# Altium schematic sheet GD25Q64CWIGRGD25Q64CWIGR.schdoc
size 127 x 101 mm
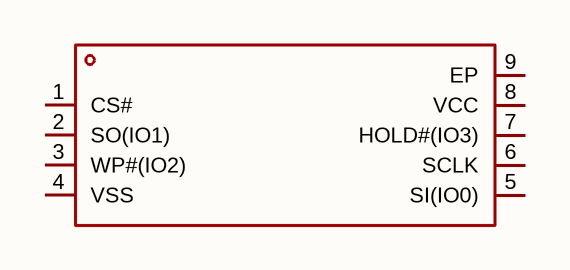
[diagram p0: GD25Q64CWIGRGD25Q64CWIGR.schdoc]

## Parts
U?  gd25q64cwigr  [WSON-8_L6.0-W5.0-P1.27-BL-EP]  (value not drawn)

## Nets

Not connected (* = marked no-connect by the designer): U? 1(CS#) 2(SO(IO1)) 3(WP#(IO2)) 4(VSS) 5(SI(IO0)) 6(SCLK) 7(HOLD#(IO3)) 8(VCC) 9(EP)

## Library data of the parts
U? = gd25q64cwigr: 接口类型:SPI;存储容量:64Mbit;时钟频率(fc):120MHz;; Manufacturer: GigaDevice(兆易创新); AddInBom: yes; ModelId: 72347fabc1e24788a361efd6527ab939; ModelName: WSON-8_L6.0-W5.0-H0.7-P1.27; ModelTransform: 237.007,196.85,0,90,0,0,0,0,0; Interface: SPI; Memory Size: 64Mbit; Clock Frequency: 120MHz; Voltage - Supply: 2.7V~3.6V; Standby Supply Current: 1uA; Program / Erase Cycles: 100000次; Page Programming Time (Tpp): 600us; Block Erase Time(tBE): 200ms@(64KB); Data Retention - TDR (Year): 20年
